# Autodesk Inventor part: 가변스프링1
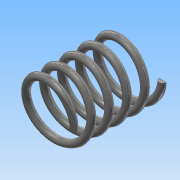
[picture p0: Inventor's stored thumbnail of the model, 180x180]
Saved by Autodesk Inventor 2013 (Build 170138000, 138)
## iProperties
Created: 2018-10
Part Number: 가변스프링1
Material: 스테인리스강
Document SubType Name: Modeling
Designer: Administrator
Density: 8.08 g/cm^3
Mass: 6.27345 g
Surface Area: 15.7634 cm^2
Volume: 0.776418 cm^3
Author: Administrator
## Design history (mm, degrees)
sketch "스케치1"
  geometry: L1 (0, 0)-(0, 25.476); L2 (0, 25.476)-(8, 25.476); L3 (0, 0)-(8, 0); C1 r 1 at (8, 0)
  constraints: 6 end point, 1 centre point, 1 coincident, 1 parallel, 1 perpendicular, 1 vertical
  dimensions: "d0" = 25.47584 distance of L1.start L1.end (derived); "d1" = 8 distance of L1.end L2.end; "d2" = 8 distance of L1.start L3.end; "d3" = 2 diameter of C1
feature "코일1" sketch "스케치1" pitch "d4" = 10; turns "d6" = 5; dims "d5" = 25.47584 (= d0), "d7" = 0, angle "d8" = 90 deg, angle "d9" = 90 deg, "d10" = 0, "d11" = 0
sketch "스케치2"
  geometry: L1 (25.476, 10)-(0, 10); L2 (0, 10)-(0, -10); L3 (0, -10)-(25.476, -10); L4 (25.476, -10)-(25.476, 10); 2 further points
  constraints: 8 end point, 2 parallel, 1 coincident, 1 horizontal, 1 midpoint, 1 perpendicular
  dimensions: "d12" = 20 distance of L3.end L1.start; "d14" = 25.47584 distance of L2.end L3.end (derived)
extrude "돌출1" sketch "스케치2" stored distance "d15" = 0; taper "d16" = 0 deg
node "솔리드1"
